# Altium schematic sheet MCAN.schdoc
size 297 x 209 mm; Symbol: Drawing-Symbol_A4; Company: 嘉立创EDA; Version: V1.0; Page Size: A4; @Project Name: 西柚在学EtherCAT; @Update Date: 2026-08-01; @Create Date: 2026-08-01; Device: Drawing-Symbol_A4; @Board Name: HPM5E3YIVK1_2; @Page Name: P1; @Create Time: 17:35:06; @Page Count: 10; @Page No: 10; @Schematic Name: HPM5E3YIVK1_2; @Update Time: 17:35:06; @Assembly Variant: Basic; Border: 1; Title Block Position: 3; Size: A4; Width: 1170; Height: 825; Region Start: 1; X Region Count: 6; Y Region Count: 4; Blade Width: 10
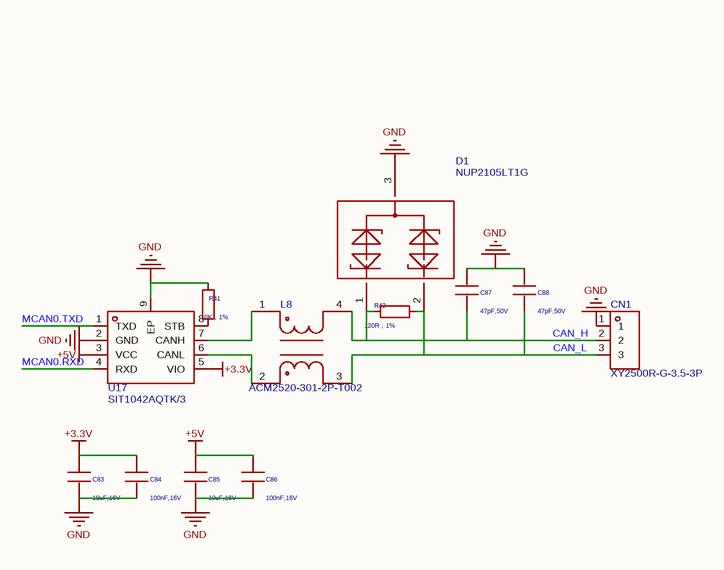
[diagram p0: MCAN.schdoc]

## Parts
C83  value 10uF,16V  [03_HPM_Capacitance:C_0402_1005Metric]
C84  value 100nF,16V  [03_HPM_Capacitance:C_0402_1005Metric]
C85  value 10uF,16V  [03_HPM_Capacitance:C_0402_1005Metric]
C86  value 100nF,16V  [03_HPM_Capacitance:C_0402_1005Metric]
C87  value 47pF,50V  [03_HPM_Capacitance:C_0402_1005Metric]
C88  value 47pF,50V  [03_HPM_Capacitance:C_0402_1005Metric]
CN1  XY2500R-G-3.5-3P  [CONN-TH_XY2500R-G-3.5-3P]
D1  NUP2105LT1G  [SOT-23-3_L2.9-W1.3-P1.90-LS2.4-BL-2]
L8  ACM2520-301-2P-T002  [FILTER-SMD_4P-L2.5-W2.0-BL]
R41  value 10K，1%  [02_HPM_Resistor:R_0402_1005Metric]
R42  value 120R，1%  [02_HPM_Resistor:R_0402_1005Metric]
U17  SIT1042AQTK/3  [TDFN-8_L3.0-W3.0-P0.65-BL-EP2.3]

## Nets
+3.3V: C83.1 C84.1 U17.5(VIO)
+5V: C85.1 C86.1 U17.3(VCC)
GND: C83.2 C84.2 C85.2 C86.2 C87.1 C88.1 CN1.1 D1.3 R41.1 U17.2(GND) U17.9(EP)
CAN_H: C87.2 CN1.2 D1.1 L8.4 R42.1
CAN_L: C88.2 CN1.3 D1.2 L8.3 R42.2
MCAN0.RXD: U17.4(RXD)
MCAN0.TXD: U17.1(TXD)
NetL8_1: L8.1 U17.7(CANH)
NetL8_2: L8.2 U17.6(CANL)
NetR41_2: R41.2 U17.8(STB)

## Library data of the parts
C83 = 电容0402: Model: CL05B104KO5NNNC; Company: SAMSUNG(三星); ki_keywords: cap capacitor; ki_description: 0402; ki_fp_filters: C_*; ID: $1I27; 3D Model: 222a10e09e6e477a9f85628e277082cb0819f05c4eef4c71ace90d822a990e87; 3D Model Transform: 39.37,19.685,19.685,0,0,0,0,0,0; AddInBom: yes; UniqueId: gge1051_15; ModelName: C0402
C84 = 电容0402: Model: CL05B104KO5NNNC; Company: SAMSUNG(三星); ki_keywords: cap capacitor; ki_description: 0402; ki_fp_filters: C_*; ID: $1I27; 3D Model: 222a10e09e6e477a9f85628e277082cb0819f05c4eef4c71ace90d822a990e87; 3D Model Transform: 39.37,19.685,19.685,0,0,0,0,0,0; AddInBom: yes; UniqueId: gge1051_16; ModelName: C0402
C85 = 电容0402: Model: CL05B104KO5NNNC; Company: SAMSUNG(三星); ki_keywords: cap capacitor; ki_description: 0402; ki_fp_filters: C_*; ID: $1I27; 3D Model: 222a10e09e6e477a9f85628e277082cb0819f05c4eef4c71ace90d822a990e87; 3D Model Transform: 39.37,19.685,19.685,0,0,0,0,0,0; AddInBom: yes; UniqueId: gge1051_17; ModelName: C0402
C86 = 电容0402: Model: CL05B104KO5NNNC; Company: SAMSUNG(三星); ki_keywords: cap capacitor; ki_description: 0402; ki_fp_filters: C_*; ID: $1I27; 3D Model: 222a10e09e6e477a9f85628e277082cb0819f05c4eef4c71ace90d822a990e87; 3D Model Transform: 39.37,19.685,19.685,0,0,0,0,0,0; AddInBom: yes; UniqueId: gge1051_18; ModelName: C0402
C87 = 电容0402: Model: CL05B104KO5NNNC; Company: SAMSUNG(三星); ki_keywords: cap capacitor; ki_description: 0402; ki_fp_filters: C_*; ID: $1I27; 3D Model: 222a10e09e6e477a9f85628e277082cb0819f05c4eef4c71ace90d822a990e87; 3D Model Transform: 39.37,19.685,19.685,0,0,0,0,0,0; AddInBom: yes; UniqueId: gge1051_19; ModelName: C0402
C88 = 电容0402: Model: CL05B104KO5NNNC; Company: SAMSUNG(三星); ki_keywords: cap capacitor; ki_description: 0402; ki_fp_filters: C_*; ID: $1I27; 3D Model: 222a10e09e6e477a9f85628e277082cb0819f05c4eef4c71ace90d822a990e87; 3D Model Transform: 39.37,19.685,19.685,0,0,0,0,0,0; AddInBom: yes; UniqueId: gge1051_20; ModelName: C0402
CN1 = XY2500R-G-3.5-3P: 连接器类型:板端/插座-闭口;结构:1x3P;间距:3.5mm;颜色:绿色;安装方式:弯插;排数:1;每排PIN数:3;额定电流:8A;额定电压:300V;工作温度:-;; Manufacturer: XINLAIYA(新莱亚); 3D Model: a990a547ac6749fd8ade1ed443a207c80819f05c4eef4c71ace90d822a990e87; 3D Model Transform: 452.755,358.267,0,0,0,0,0,-124.016,-137.795; Number of Positions or Pins: 1x3P; Pitch: 3.5mm; Number of PINs Per Row: 3; Current Rating: 8A; Voltage Rating (Max): 300V; AddInBom: yes
D1 = NUP2105LT1G_C14486: 极性:双向;反向截止电压(Vrwm):24V;钳位电压:44V;峰值脉冲电流(Ipp):8A@8/20us;峰值脉冲功率(Ppp):350W@8/20us;击穿电压:32V;; Manufacturer: onsemi(安森美); AddInBom: yes; ModelId: 115ef394a879442d90491e61279301380819f05c4eef4c71ace90d822a990e87; ModelName: SOT-23-3_L2.9-W1.3-P1.90-LS2.4; ModelTransform: 114.173,94.488,0,0,0,0,0,0,0; Polarity: 双向; Reverse Stand-Off Voltage (Vrwm): 24V; Clamping Voltage: 44V; Voltage - Breakdown: 32V; Reverse Leakage Current (Ir): 100nA; Number of Channels: 双路; level of protection: IEC 61000-4-4；IEC 61000-4-5；IEC 61000-4-2; Type: TVS; Junction Capacitance: 30pF
L8 = ACM2520-301-2P-T002: 通道数:2;电感@频率:-;阻抗@频率:300Ω@100MHz;直流电阻(DCR):350mΩ;; Manufacturer: TDK; AddInBom: yes; ModelId: afa23f7d380e4ec3b0c60d44c06c49fe0819f05c4eef4c71ace90d822a990e87; ModelName: FILTER-SMD_4P-L2.5-W2.0-H1.2-P1.3; ModelTransform: 99.2124,78.74,0,0,0,0,0,-0.005,0; Number of Lines: 2; Current Rating: 400mA; Voltage Rating - DC: 20V; DC Resistance(DCR): 350mΩ; Insulation Resistance(IR): 10MΩ
R41 = 电阻0402: Model: 0402WGF1002TCE; Company: UNI-ROYAL(厚声); ki_keywords: R res resistor; ki_description: Resistor; ki_fp_filters: R_*; ID: $3I57; 3D Model: 98c88bc2b9094f218f3a3e30a70127380819f05c4eef4c71ace90d822a990e87; 3D Model Transform: 39.37,19.685,14.173200563192367,0,0,0,0,0,0; AddInBom: yes; UniqueId: 469542c170a520e3_21; ModelName: R0402_L1.0-W0.5-H0.4
R42 = 电阻0402: Model: 0402WGF1002TCE; Company: UNI-ROYAL(厚声); ki_keywords: R res resistor; ki_description: Resistor; ki_fp_filters: R_*; ID: $3I57; 3D Model: 98c88bc2b9094f218f3a3e30a70127380819f05c4eef4c71ace90d822a990e87; 3D Model Transform: 39.37,19.685,14.173200563192367,0,0,0,0,0,0; AddInBom: yes; UniqueId: 469542c170a520e3_22; ModelName: R0402_L1.0-W0.5-H0.4
U17 = SIT1042AQTK/3: 类型:CAN-FD收发器;数据速率:5Mbps;; Manufacturer: SIT(芯力特); AddInBom: yes; ModelId: 87cbd0851a6d45bba9a717edfc43b2c90819f05c4eef4c71ace90d822a990e87; ModelTransform: 118.11,118.8974,0,0,0,0,0,0,0; Data Rate: 5Mbps; Voltage - Supply: 4.5V~5.5V; Current - Supply: 70mA; Quiescent Supply Current: 500nA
